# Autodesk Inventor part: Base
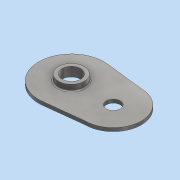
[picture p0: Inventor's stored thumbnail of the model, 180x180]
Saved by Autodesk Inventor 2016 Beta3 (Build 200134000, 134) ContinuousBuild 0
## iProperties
Created: 2015-11
Part Number: Base
Material: Aluminum 6061-AHC
Document SubType Name: Modeling
Designer: SanPer86
Density: 2.7 g/cm^3
Appearance: Aluminum - Dark
Mass: 0.0633333 g
Surface Area: 1.39666 cm^2
Volume: 0.0234568 cm^3
Author: SanPer86
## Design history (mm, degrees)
sketch "Sketch1"
  geometry: L1 (4.513, 3)-(0.378, 3.48); L2 (4.513, -2.996)-(0.576, -3.452); L3 (0.576, -3.452)-(0.378, -3.475); C1 r 0.75 at (4.5, 0); A1 r 3.5 centre (0, 0) between (0.429, 3.474) and (0.576, -3.452); A2 r 3 centre (4.5, 0) between (2.611, 2.331) and (4.477, -3); A3 r 3 centre (4.5, 0) between (4.513, 3) and (2.611, 2.331); A4 r 3 centre (4.5, 0) between (4.477, -3) and (4.513, 3); A5 r 3.5 centre (0, 0) between (2.611, 2.331) and (0.429, 3.474); A6 r 3.5 centre (0, 0) between (0.576, -3.452) and (2.611, 2.331); 1 further point
  constraints: 14 point on circle, 7 centre point, 6 end point, 2 coincident, 2 point on line
  dimensions: "d0" = 7 diameter of A1; "d1" = 6 diameter of A2; "d2" = 4.5 distance of A2.centre point (0, 0); "d3" = 1.5 diameter of C1
extrude "Extrusion1" new body sketch "Sketch1" distance "d5" = 0.375; taper "d6" = 0 deg
sketch "Sketch2"
  geometry: C1 r 1.375 at (0, 0); 1 further point
  constraints: 1 centre point, 1 coincident
  dimensions: "d7" = 2.75 diameter of C1
extrude "Extrusion2" join sketch "Sketch2" distance "d8" = 0.625; taper "d9" = 0 deg
sketch "Sketch3"
  geometry: C1 r 1 at (0, 0); 1 further point
  constraints: 1 centre point, 1 coincident
  dimensions: "d10" = 2 diameter of C1
extrude "Extrusion3" cut sketch "Sketch3" stored distance "d11" = 0.625; taper "d12" = 0 deg
fillet "Fillet1" dims "d13" = 0.125
body "Solid1"
